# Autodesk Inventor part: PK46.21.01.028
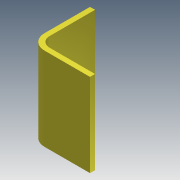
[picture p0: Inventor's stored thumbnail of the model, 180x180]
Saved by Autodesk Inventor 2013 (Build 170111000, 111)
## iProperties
Created: 2005-04
Part Number: PK46.21.01.028
Material: Steel, Mild
Document SubType Name: Sheet Metal
Designer: salex
Manufacturer: Standard
Standards Organization: Custom
Density: 7.86 g/cm^3
Sheet Metal Rule: Default
Author: salex
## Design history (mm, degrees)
node "ФлнОтгиб1"
body "Solid1"
sketch "Эскиз1"
  geometry: L1 (0, 0)-(0, -110); L2 (0, -110)-(110, -110)
  constraints: 4 end point, 1 perpendicular, 1 vertical, 1 other
  dimensions: "d0" = 110 distance of L1.start L1.end; "d1" = 110 distance of L1.end L2.end
feature "Плакирование1" dims "d2" = 165, "d3" = 10 (= BendReliefWidth), "d5" = 20 (= MinimumRemnant), "d7" = 20 (= BendRadius), "d8" = 10, "Thickness" = 10
feature "Изгиб1" dims "d3" = 10 (= BendReliefWidth), "d4" = 5 (= BendReliefDepth), "d5" = 20 (= MinimumRemnant), "d6" = 20 (= BendRadius), "d7" = 20 (= BendRadius), "d8" = 10, "SeamGap" = 0.01, "Thickness" = 10
other parameters: "BendRadius" = 20, "BendReliefDepth" = 5 (= 0.5 x Thickness)
